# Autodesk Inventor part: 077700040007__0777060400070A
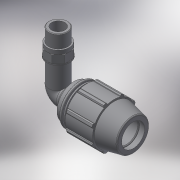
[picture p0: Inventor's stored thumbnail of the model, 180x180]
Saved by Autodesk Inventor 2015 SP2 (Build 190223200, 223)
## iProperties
Created: 2017-02
Part Number: 077700040007__0777060400070A
Material: Generic
Description: PLASSON 90° ELBOW MALE WITH INTEGRAL BRASS THREAD 40-3/4"
Document SubType Name: Modeling
Designer: KIM
Mass: 174.249 g
Surface Area: 431.906 cm^2
Volume: 174.249 cm^3
Density: 1 g/cm^3
Appearance: Default
Author: KIM
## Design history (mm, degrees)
derived "07770.ipt"
feature "Solid1::07770.ipt"
tag "TaggingFeature1"
body "Solid1"
other parameters: "d4" = 10.33333, "d5" = 31, "d7" = 82, "d9" = 17.71429, "d11" = 4.13333, "d13" = 120 deg, "d14" = 56, "d15" = 12 deg, "d16" = 71.34, "d18" = 2, "d19" = 35 deg, "d20" = 17.5 deg, "d21" = 76.26, "d23" = 0, "d25" = 360 deg, "d27" = 1.64, "d33" = 0.8, "d42" = 45.88, "d43" = 2.46, "d46" = 1.2, "d51" = 124, "d68" = 8.26667, "d72" = 86, "d73" = 26.441, "d74" = 18, "d75" = 30.40715, "d76" = 18.5087, "d79" = 10.5764, "d80" = 0.79323, "d83" = 0, "d84" = 0, "d91" = 61.5, "d93" = 84, "d94" = 26.441, "d95" = 18.5087, "d96" = 8.26667, "d97" = 50 deg, "d98" = 2.06667, "d99" = 69.1998, "d100" = 2.06667, "d101" = 2.06667, "d105" = 1.8, "d106" = 31.7292, "d107" = 18, "d108" = 10.8, "d109" = 0, "E_" = 82, "A_" = 124, "l_" = 84, "l_2" = 18, "A_1" = 86, "R_" = 26.441
